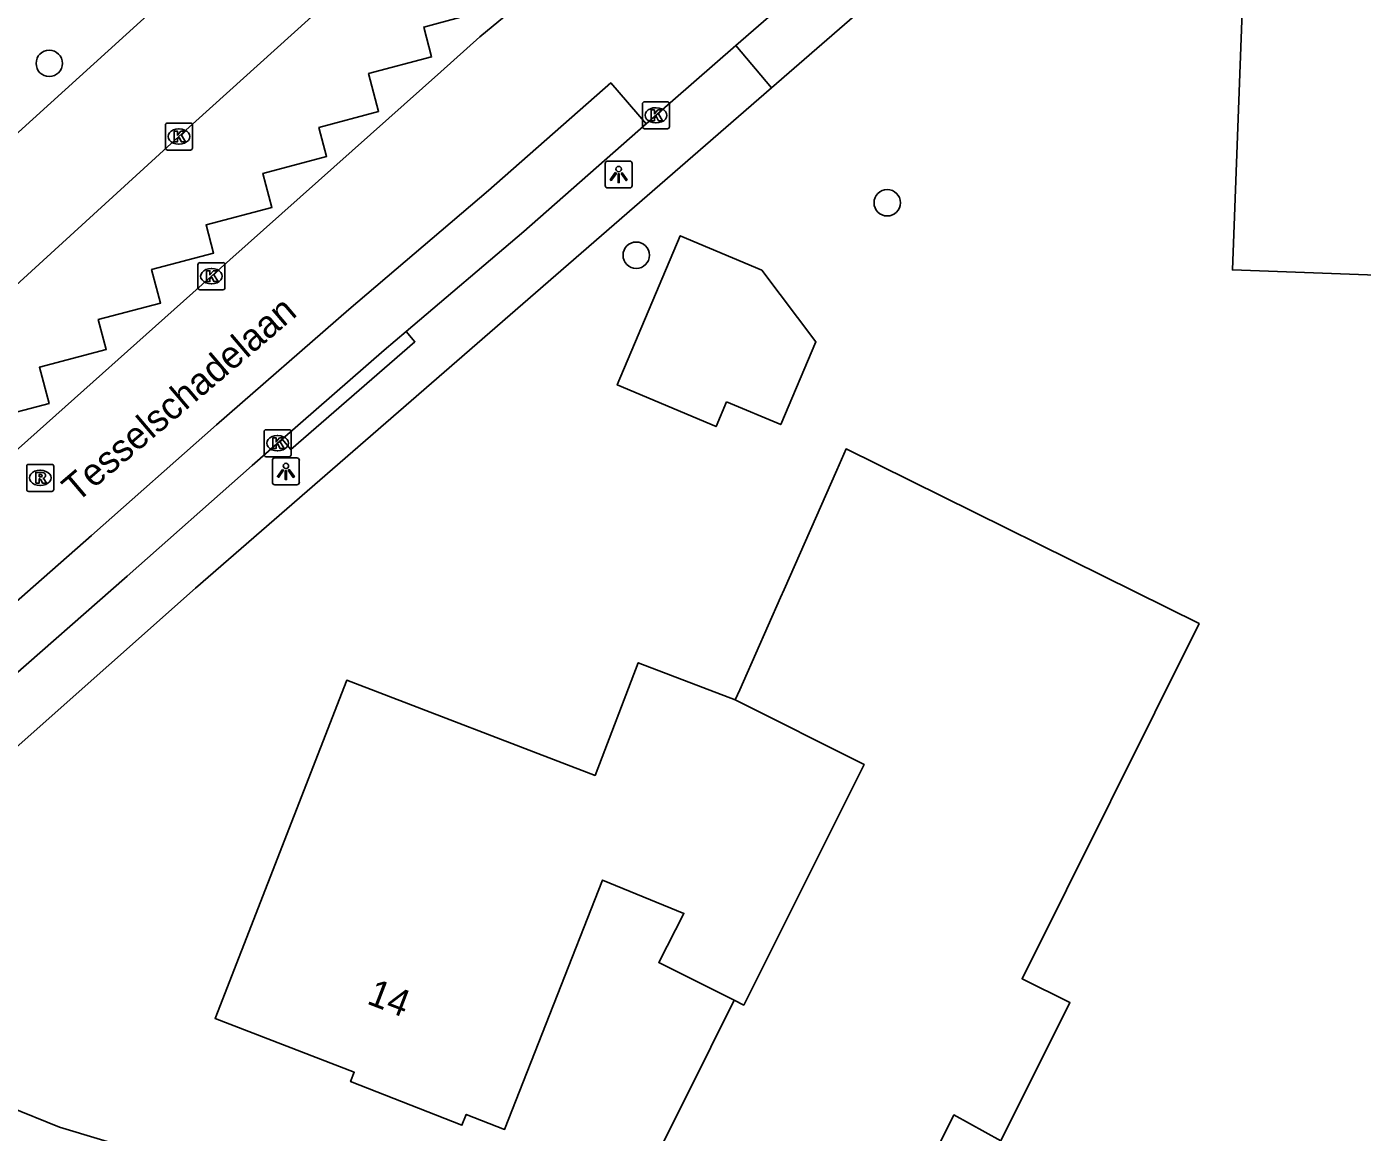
# Model space of a CAD drawing. Extents: x 161354 to 161876, y 382161 to 382804.
# Drawn here: x 161674.87 to 161724.32, y 382511.32 to 382552.26 of the extents above; entities that cross this region are included whole.
import ezdxf

# ---------------------------------------------------------------- set-up
doc = ezdxf.new("R2010")
doc.units = 0
for name, color, linetype in [('IMGEO_Boom', 7, 'Continuous'), ('IMGEO_Kolk', 7, 'Continuous'), ('IMGEO_Lichtpunt', 7, 'Continuous'), ('IMGEO_Openbare_ruimte_label', 7, 'Continuous'), ('IMGEO_Pand', 7, 'Continuous'), ('IMGEO_Pand_nummerreeks', 7, 'Continuous'), ('IMGEO_Parkeervlak_open', 7, 'Continuous'), ('IMGEO_Rijbaan_lokaal_gesloten', 7, 'Continuous'), ('IMGEO_Rijbaan_lokaal_open', 7, 'Continuous'), ('IMGEO_Rioolput', 7, 'Continuous'), ('IMGEO_Voetpad_open', 7, 'Continuous')]:
    doc.layers.add(name, color=color, linetype=linetype)

msp = doc.modelspace()

# ---------------------------------------------------------------- linework, layer by layer
at = {"layer": 'IMGEO_Boom'}
for centre in [(161675.705, 382550.908), (161706.733, 382545.744), (161697.439, 382543.801)]:
    msp.add_circle(centre, 0.489, dxfattribs=at)
at = {"layer": 'IMGEO_Kolk'}
for p, q in [((161697.669, 382548.558), (161697.669, 382549.41)), ((161697.744, 382549.484), (161698.596, 382549.484)), ((161698.157, 382549.264), (161698.182, 382549.264)), ((161698.67, 382549.41), (161698.67, 382548.558)), ((161680.006, 382547.771), (161680.006, 382548.623)), ((161680.081, 382548.697), (161680.933, 382548.697)), ((161680.494, 382548.477), (161680.519, 382548.477)), ((161681.007, 382548.623), (161681.007, 382547.771)), ((161698.596, 382548.484), (161697.744, 382548.484)), ((161698.18, 382548.704), (161698.155, 382548.704)), ((161680.517, 382547.917), (161680.492, 382547.917)), ((161680.933, 382547.697), (161680.081, 382547.697)), ((161681.21, 382542.6), (161681.21, 382543.452)), ((161681.285, 382543.526), (161682.137, 382543.526)), ((161681.698, 382543.306), (161681.723, 382543.306)), ((161682.211, 382543.452), (161682.211, 382542.6)), ((161682.137, 382542.526), (161681.285, 382542.526)), ((161681.721, 382542.746), (161681.696, 382542.746)), ((161683.658, 382536.415), (161683.658, 382537.267)), ((161683.733, 382537.341), (161684.585, 382537.341)), ((161684.146, 382537.121), (161684.171, 382537.121)), ((161684.659, 382537.267), (161684.659, 382536.415)), ((161684.169, 382536.561), (161684.144, 382536.561)), ((161684.585, 382536.341), (161683.733, 382536.341))]:
    msp.add_line(p, q, dxfattribs=at)
for points in [[(161697.669, 382548.558), (161697.669, 382549.41)], [(161697.744, 382549.484), (161698.596, 382549.484)], [(161698.67, 382549.41), (161698.67, 382548.558)], [(161697.99, 382549.184), (161698.113, 382549.184), (161698.113, 382549.033), (161698.243, 382549.184), (161698.407, 382549.184), (161698.261, 382549.033), (161698.414, 382548.784), (161698.262, 382548.784), (161698.177, 382548.948), (161698.113, 382548.881), (161698.113, 382548.784), (161697.99, 382548.784), (161697.99, 382549.184)], [(161680.006, 382547.771), (161680.006, 382548.623)], [(161680.081, 382548.697), (161680.933, 382548.697)], [(161680.327, 382548.397), (161680.45, 382548.397), (161680.45, 382548.246), (161680.58, 382548.397), (161680.744, 382548.397), (161680.598, 382548.246), (161680.751, 382547.997), (161680.599, 382547.997), (161680.514, 382548.161), (161680.45, 382548.094), (161680.45, 382547.997), (161680.327, 382547.997), (161680.327, 382548.397)], [(161681.007, 382548.623), (161681.007, 382547.771)], [(161698.596, 382548.484), (161697.744, 382548.484)], [(161680.933, 382547.697), (161680.081, 382547.697)], [(161681.21, 382542.6), (161681.21, 382543.452)], [(161681.285, 382543.526), (161682.137, 382543.526)], [(161682.211, 382543.452), (161682.211, 382542.6)], [(161681.531, 382543.226), (161681.654, 382543.226), (161681.654, 382543.075), (161681.784, 382543.226), (161681.948, 382543.226), (161681.802, 382543.075), (161681.955, 382542.826), (161681.803, 382542.826), (161681.718, 382542.99), (161681.654, 382542.923), (161681.654, 382542.826), (161681.531, 382542.826), (161681.531, 382543.226)], [(161682.137, 382542.526), (161681.285, 382542.526)], [(161683.658, 382536.415), (161683.658, 382537.267)], [(161683.733, 382537.341), (161684.585, 382537.341)], [(161683.979, 382537.041), (161684.102, 382537.041), (161684.102, 382536.89), (161684.232, 382537.041), (161684.396, 382537.041), (161684.25, 382536.89), (161684.403, 382536.641), (161684.251, 382536.641), (161684.166, 382536.805), (161684.102, 382536.738), (161684.102, 382536.641), (161683.979, 382536.641), (161683.979, 382537.041)], [(161684.659, 382537.267), (161684.659, 382536.415)], [(161684.585, 382536.341), (161683.733, 382536.341)]]:
    msp.add_lwpolyline(points, dxfattribs=at)
for centre, start, end in [((161697.746, 382549.408), 91.552, 178.448), ((161697.746, 382549.408), 91.552, 178.448), ((161698.594, 382549.408), 1.552, 88.448), ((161698.594, 382549.408), 1.552, 88.448), ((161680.083, 382548.621), 91.552, 178.448), ((161680.083, 382548.621), 91.552, 178.448), ((161680.931, 382548.621), 1.552, 88.448), ((161680.931, 382548.621), 1.552, 88.448), ((161697.746, 382548.56), 181.552, 268.448), ((161697.746, 382548.56), 181.552, 268.448), ((161698.594, 382548.56), 271.552, 358.448), ((161698.594, 382548.56), 271.552, 358.448), ((161680.083, 382547.773), 181.552, 268.448), ((161680.083, 382547.773), 181.552, 268.448), ((161680.931, 382547.773), 271.552, 358.448), ((161680.931, 382547.773), 271.552, 358.448), ((161681.287, 382543.45), 91.552, 178.448), ((161681.287, 382543.45), 91.552, 178.448), ((161682.135, 382543.45), 1.552, 88.448), ((161682.135, 382543.45), 1.552, 88.448), ((161681.287, 382542.602), 181.552, 268.448), ((161681.287, 382542.602), 181.552, 268.448), ((161682.135, 382542.602), 271.552, 358.448), ((161682.135, 382542.602), 271.552, 358.448), ((161683.735, 382537.265), 91.552, 178.448), ((161683.735, 382537.265), 91.552, 178.448), ((161684.583, 382537.265), 1.552, 88.448), ((161684.583, 382537.265), 1.552, 88.448), ((161683.735, 382536.417), 181.552, 268.448), ((161683.735, 382536.417), 181.552, 268.448), ((161684.583, 382536.417), 271.552, 358.448), ((161684.583, 382536.417), 271.552, 358.448)]:
    msp.add_arc(centre, 0.0765, start, end, dxfattribs=at)
for centre, major_axis, ratio, start_param, end_param in [((161698.156, 382548.984), (-0.387, 0.002), 0.722429, 4.712389, 7.853982), ((161698.181, 382548.984), (-0.39, 0.002), 0.717154, 1.570796, 4.712389), ((161680.493, 382548.197), (-0.387, 0.002), 0.722429, 4.712389, 7.853982), ((161680.518, 382548.197), (-0.39, 0.002), 0.717154, 1.570796, 4.712389), ((161681.697, 382543.026), (-0.387, 0.002), 0.722429, 4.712389, 7.853982), ((161681.722, 382543.026), (-0.39, 0.002), 0.717154, 1.570796, 4.712389), ((161684.145, 382536.841), (-0.387, 0.002), 0.722429, 4.712389, 7.853982), ((161684.17, 382536.841), (-0.39, 0.002), 0.717154, 1.570796, 4.712389)]:
    msp.add_ellipse(centre, major_axis=major_axis, ratio=ratio, start_param=start_param, end_param=end_param, dxfattribs=at)
at = {"layer": 'IMGEO_Lichtpunt'}
for p, q in [((161697.191, 382547.291), (161696.383, 382547.291)), ((161697.191, 382547.291), (161696.383, 382547.291)), ((161696.289, 382547.196), (161696.289, 382546.389)), ((161696.289, 382547.196), (161696.289, 382546.389)), ((161697.285, 382546.389), (161697.285, 382547.196)), ((161697.285, 382546.389), (161697.285, 382547.196)), ((161696.383, 382546.295), (161697.191, 382546.295)), ((161696.383, 382546.295), (161697.191, 382546.295)), ((161683.968, 382536.201), (161683.968, 382535.394)), ((161683.968, 382536.201), (161683.968, 382535.394)), ((161684.87, 382536.296), (161684.062, 382536.296)), ((161684.87, 382536.296), (161684.062, 382536.296)), ((161684.964, 382535.394), (161684.964, 382536.201)), ((161684.964, 382535.394), (161684.964, 382536.201)), ((161684.062, 382535.3), (161684.87, 382535.3)), ((161684.062, 382535.3), (161684.87, 382535.3))]:
    msp.add_line(p, q, dxfattribs=at)
for points in [[(161696.663, 382546.86), (161696.702, 382546.832), (161696.514, 382546.57), (161696.476, 382546.597), (161696.663, 382546.86)], [(161696.765, 382546.812), (161696.812, 382546.812), (161696.812, 382546.49), (161696.765, 382546.49), (161696.765, 382546.812)], [(161696.875, 382546.832), (161696.913, 382546.859), (161697.1, 382546.597), (161697.061, 382546.569), (161696.875, 382546.832)], [(161684.342, 382535.865), (161684.381, 382535.837), (161684.193, 382535.575), (161684.155, 382535.602), (161684.342, 382535.865)], [(161684.554, 382535.837), (161684.592, 382535.864), (161684.779, 382535.602), (161684.74, 382535.574), (161684.554, 382535.837)], [(161684.444, 382535.817), (161684.491, 382535.817), (161684.491, 382535.495), (161684.444, 382535.495), (161684.444, 382535.817)]]:
    msp.add_lwpolyline(points, dxfattribs=at)
for centre in [(161696.788, 382546.994), (161684.467, 382535.999)]:
    msp.add_circle(centre, 0.0994, dxfattribs=at)
for centre, start, end in [((161696.383, 382547.196), 90, 180), ((161696.383, 382547.196), 90, 180), ((161697.191, 382547.196), 0, 90), ((161697.191, 382547.196), 0, 90), ((161696.383, 382546.389), 180, 270), ((161696.383, 382546.389), 180, 270), ((161697.191, 382546.389), 270, 0), ((161697.191, 382546.389), 270, 360), ((161684.062, 382536.201), 90, 180), ((161684.062, 382536.201), 90, 180), ((161684.87, 382536.201), 0, 90), ((161684.87, 382536.201), 0, 90), ((161684.062, 382535.394), 180, 270), ((161684.062, 382535.394), 180, 270), ((161684.87, 382535.394), 270, 0), ((161684.87, 382535.394), 270, 360)]:
    msp.add_arc(centre, 0.0946, start, end, dxfattribs=at)
at = {"layer": 'IMGEO_Pand'}
for points in [[(161735.075, 382528.457), (161734.18, 382530.69), (161749.331, 382536.762), (161748.369, 382539.161), (161750.406, 382539.978), (161752.228, 382539.889), (161752.332, 382542.029), (161724.511, 382543.072), (161719.514, 382543.259), (161720.16, 382560.416), (161766.754, 382558.659), (161766.519, 382552.424), (161766.277, 382545.989), (161766.108, 382541.512), (161761.112, 382541.699), (161755.002, 382541.928), (161754.713, 382535.995)], [(161700.783, 382538.377), (161700.393, 382537.454), (161696.736, 382539.001), (161699.071, 382544.523), (161702.085, 382543.248), (161704.089, 382540.596), (161702.791, 382537.528), (161700.783, 382538.377)], [(161701.108, 382527.333), (161701.274, 382527.709), (161701.407, 382528.011), (161702.78, 382531.122), (161702.913, 382531.424), (161704.863, 382535.846), (161705.209, 382536.63), (161718.281, 382530.16), (161711.723, 382517.008), (161713.495, 382516.124), (161710.939, 382510.999), (161709.201, 382511.967), (161705.646, 382504.803), (161704.346, 382505.443), (161703.935, 382504.612), (161698.261, 382507.398), (161698.673, 382508.24), (161697.4, 382508.875), (161699.331, 382512.737), (161701.067, 382516.209)], [(161701.067, 382516.209), (161698.645, 382517.421), (161698.274, 382517.607), (161699.202, 382519.424), (161696.188, 382520.662), (161692.567, 382511.427), (161691.144, 382511.985), (161690.987, 382511.583), (161686.863, 382513.2), (161686.999, 382513.547), (161681.847, 382515.536), (161686.722, 382528.062), (161695.912, 382524.537), (161697.513, 382528.711), (161701.108, 382527.333)], [(161701.108, 382527.333), (161705.884, 382524.94), (161701.422, 382516.032), (161701.067, 382516.209)]]:
    msp.add_lwpolyline(points, dxfattribs=at)
at = {"layer": 'IMGEO_Parkeervlak_open'}
msp.add_lwpolyline([(161694.116, 382554.765), (161691.774, 382554.142), (161692.098, 382552.924), (161690.119, 382552.398), (161689.571, 382552.252), (161689.864, 382551.148), (161687.527, 382550.526), (161687.9, 382549.123), (161685.689, 382548.535), (161685.975, 382547.461), (161683.612, 382546.833), (161683.948, 382545.572), (161681.511, 382544.924), (161681.789, 382543.88), (161679.495, 382543.27), (161679.825, 382542.031), (161677.519, 382541.417), (161677.813, 382540.311), (161675.339, 382539.653), (161675.696, 382538.314), (161673.531, 382537.738)], dxfattribs=at)
at = {"layer": 'IMGEO_Rijbaan_lokaal_gesloten'}
for points in [[(161701.128, 382551.574), (161703.639, 382553.768), (161707.699, 382557.212)], [(161694.524, 382554.274), (161691.651, 382551.884), (161690.206, 382550.598), (161681.712, 382543.025), (161666.712, 382529.643)], [(161697.808, 382548.669), (161698.795, 382549.536), (161701.128, 382551.574)], [(161670.597, 382524.931), (161669.286, 382526.443), (161672.516, 382529.253), (161677.271, 382533.418), (161681.896, 382537.521), (161686.794, 382541.797), (161691.965, 382546.197), (161696.498, 382550.18), (161697.808, 382548.669)]]:
    msp.add_lwpolyline(points, dxfattribs=at)
at = {"layer": 'IMGEO_Rijbaan_lokaal_open'}
for points in [[(161682.265, 382559.016), (161684.128, 382557.046), (161652.099, 382527.995)], [(161653.308, 382523.528), (161654.315, 382524.377), (161662.915, 382532.2), (161671.874, 382540.317), (161680.506, 382548.198), (161692.48, 382559.009)]]:
    msp.add_lwpolyline(points, dxfattribs=at)
at = {"layer": 'IMGEO_Rioolput'}
for p, q in [((161674.869, 382535.131), (161674.869, 382535.983)), ((161674.944, 382536.057), (161675.796, 382536.057)), ((161675.87, 382535.983), (161675.87, 382535.131)), ((161675.357, 382535.837), (161675.382, 382535.837)), ((161675.796, 382535.057), (161674.944, 382535.057)), ((161675.38, 382535.277), (161675.355, 382535.277))]:
    msp.add_line(p, q, dxfattribs=at)
for points in [[(161674.869, 382535.131), (161674.869, 382535.983)], [(161674.944, 382536.057), (161675.796, 382536.057)], [(161675.87, 382535.983), (161675.87, 382535.131)], [(161675.458, 382535.755), (161675.206, 382535.757), (161675.206, 382535.357)], [(161675.206, 382535.357), (161675.33, 382535.357), (161675.33, 382535.519), (161675.341, 382535.519)], [(161675.384, 382535.676), (161675.33, 382535.676), (161675.33, 382535.595)], [(161675.33, 382535.595), (161675.382, 382535.595)], [(161675.388, 382535.49), (161675.459, 382535.357), (161675.599, 382535.357), (161675.534, 382535.483)], [(161675.796, 382535.057), (161674.944, 382535.057)]]:
    msp.add_lwpolyline(points, dxfattribs=at)
for centre, radius, start, end in [((161674.946, 382535.981), 0.0765, 91.552, 178.448), ((161674.946, 382535.981), 0.0765, 91.552, 178.448), ((161675.794, 382535.981), 0.0765, 1.552, 88.448), ((161675.794, 382535.981), 0.0765, 1.552, 88.448), ((161675.34, 382535.466), 0.0533, 26.0293, 88.6989), ((161675.366, 382535.784), 0.19, 274.7715, 282.9687), ((161675.39, 382535.58), 0.0964, 77.0061, 93.1865), ((161675.404, 382535.637), 0.0378, 276.6634, 79.6772), ((161675.457, 382535.645), 0.109, 350.3612, 89.416), ((161675.455, 382535.645), 0.112, 277.5842, 350.9817), ((161675.439, 382535.43), 0.108, 29.5134, 73.7905), ((161674.946, 382535.133), 0.0765, 181.552, 268.448), ((161674.946, 382535.133), 0.0765, 181.552, 268.448), ((161675.794, 382535.133), 0.0765, 271.552, 358.448), ((161675.794, 382535.133), 0.0765, 271.552, 358.448)]:
    msp.add_arc(centre, radius, start, end, dxfattribs=at)
for centre, major_axis, ratio, start_param, end_param in [((161675.356, 382535.557), (-0.387, 0.002), 0.722429, 4.712389, 7.853982), ((161675.381, 382535.557), (-0.39, 0.002), 0.717154, 1.570796, 4.712389)]:
    msp.add_ellipse(centre, major_axis=major_axis, ratio=ratio, start_param=start_param, end_param=end_param, dxfattribs=at)
at = {"layer": 'IMGEO_Voetpad_open'}
for points in [[(161709.058, 382555.75), (161702.444, 382550.002)], [(161702.444, 382550.002), (161701.128, 382551.574)], [(161702.444, 382550.002), (161681.121, 382531.471), (161671.366, 382522.817), (161670.351, 382521.638), (161669.529, 382520.317)], [(161697.808, 382548.669), (161693.273, 382544.684), (161688.915, 382540.975)], [(161688.915, 382540.975), (161689.242, 382540.598), (161684.655, 382536.613), (161684.328, 382536.99)], [(161684.328, 382536.99), (161688.1, 382540.282), (161688.915, 382540.975)], [(161684.328, 382536.99), (161683.217, 382536.02), (161678.594, 382531.918), (161673.831, 382527.746), (161670.597, 382524.931)], [(161671.192, 382513.811), (161672.294, 382513.039), (161676.079, 382511.506), (161686.582, 382508.346), (161693.296, 382505.713), (161699.526, 382502.596), (161701.857, 382501.312), (161704.194, 382500.041), (161707.056, 382498.523), (161714.17, 382494.92), (161716.027, 382493.968), (161718.402, 382492.765), (161721.484, 382491.299)]]:
    msp.add_lwpolyline(points, dxfattribs=at)

# ---------------------------------------------------------------- texts
at = {"layer": 'IMGEO_Openbare_ruimte_label'}
msp.add_text('Tesselschadelaan', height=1, rotation=40.3776, dxfattribs=at).set_placement((161676.722, 382534.614))
at = {"layer": 'IMGEO_Pand_nummerreeks'}
msp.add_text('14', height=1, rotation=339.0281, dxfattribs=at).set_placement((161687.423, 382516.098))

doc.saveas('drawing.dxf')
